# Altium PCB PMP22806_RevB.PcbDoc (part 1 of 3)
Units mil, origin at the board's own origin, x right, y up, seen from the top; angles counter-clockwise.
Board outline 5500 x 3040 mil, 4 copper layers (Top Layer, Signal Layer 1, Signal Layer 2, Bottom Layer), stack 61.2 mil thick; 196 components, 100 nets, 518 pads, 186 vias.
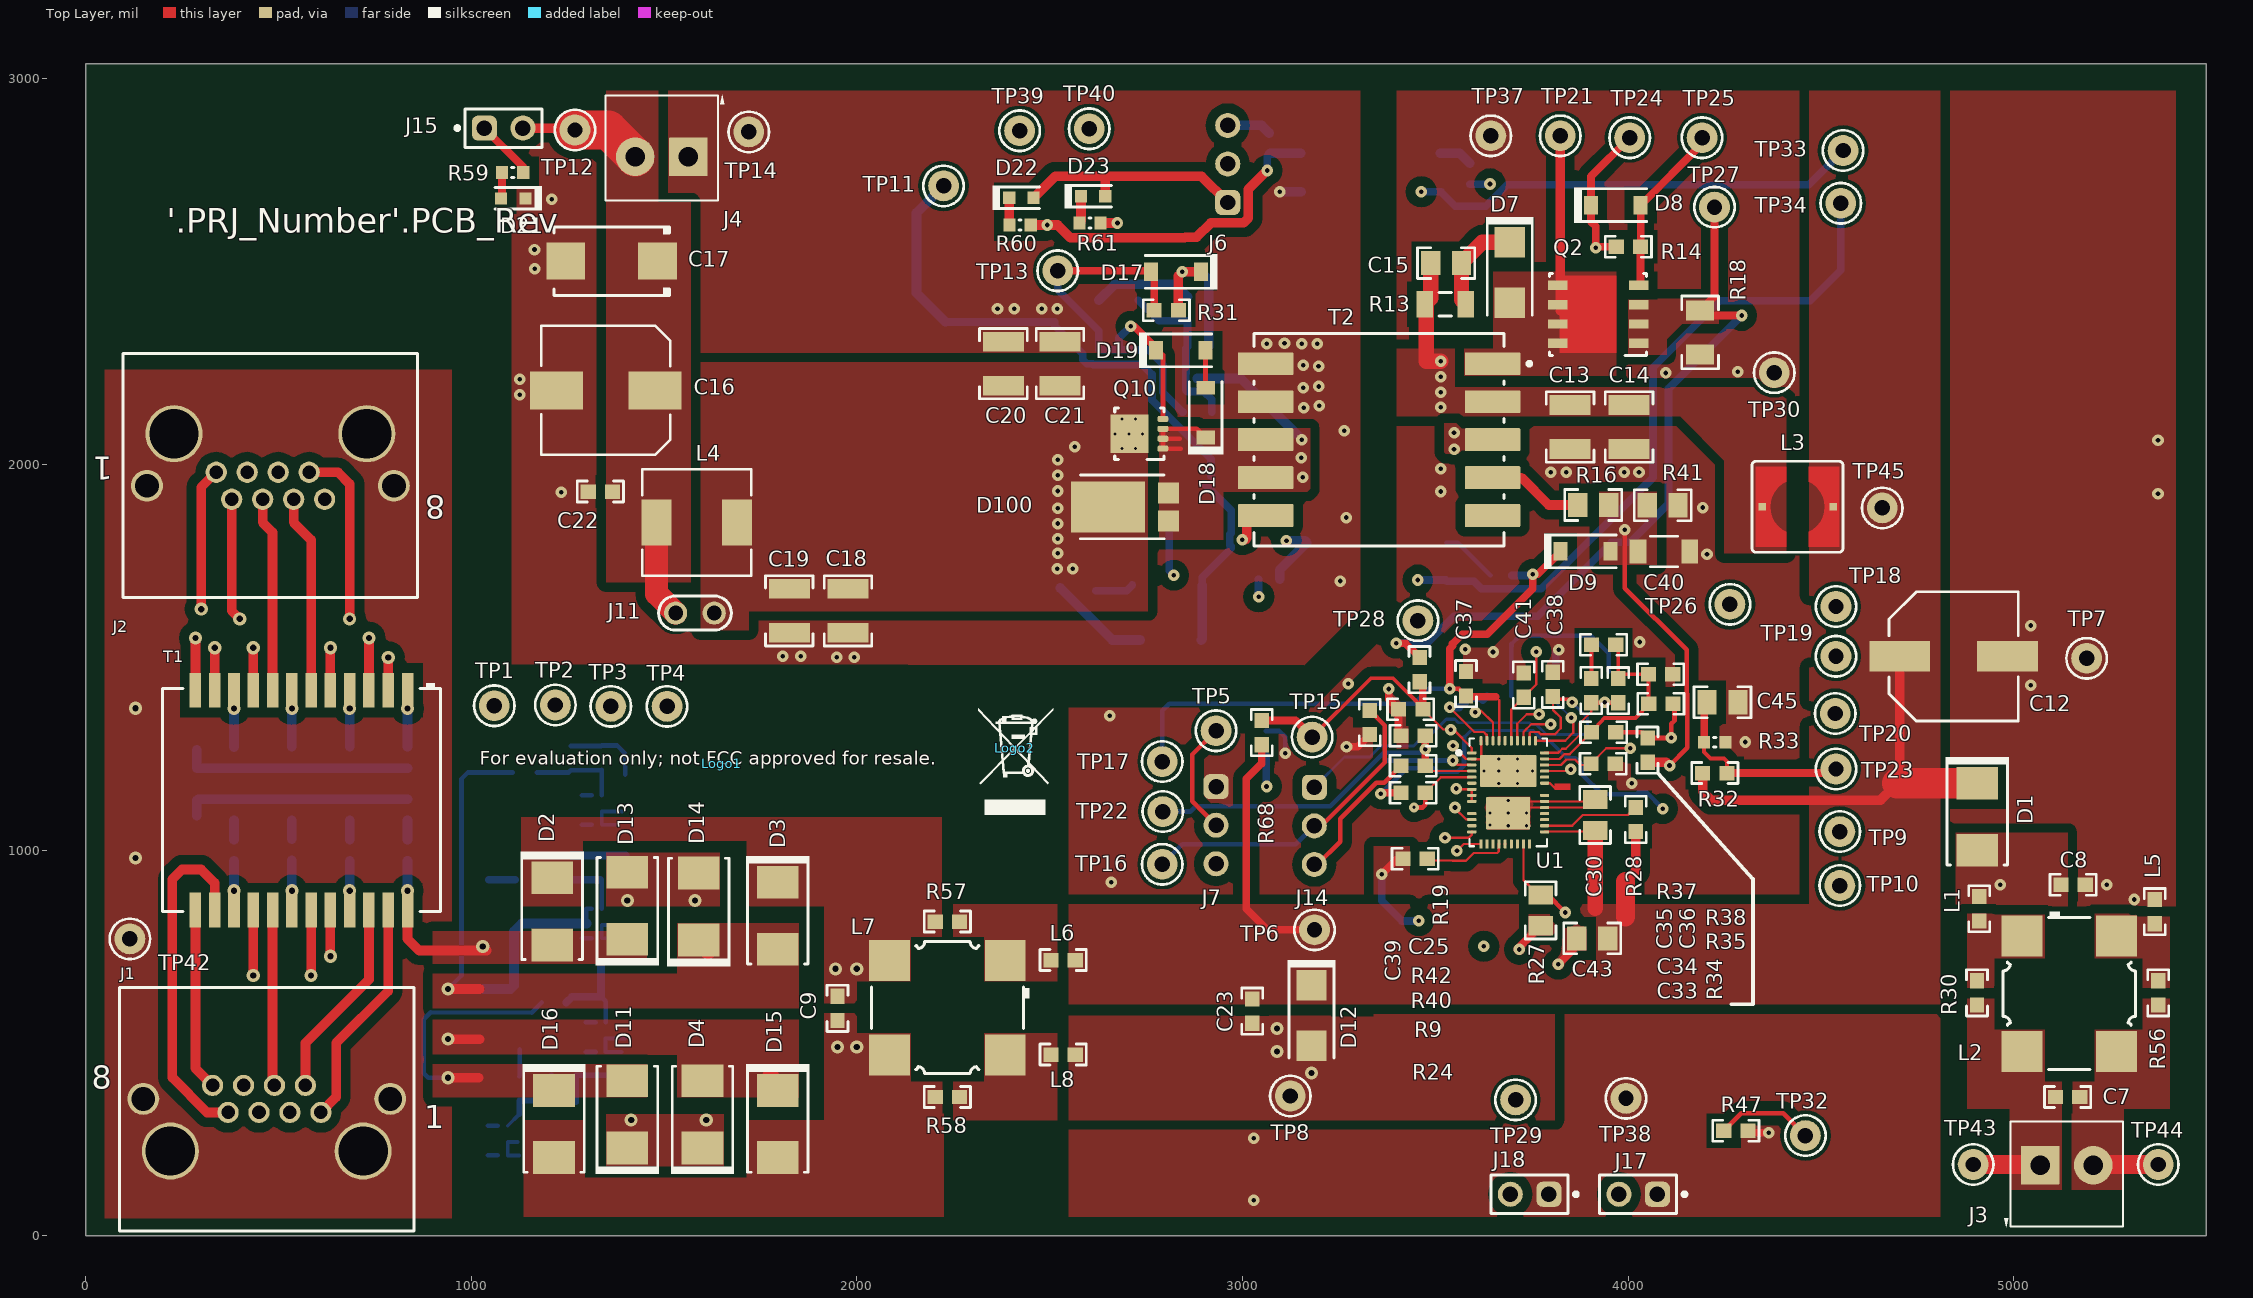
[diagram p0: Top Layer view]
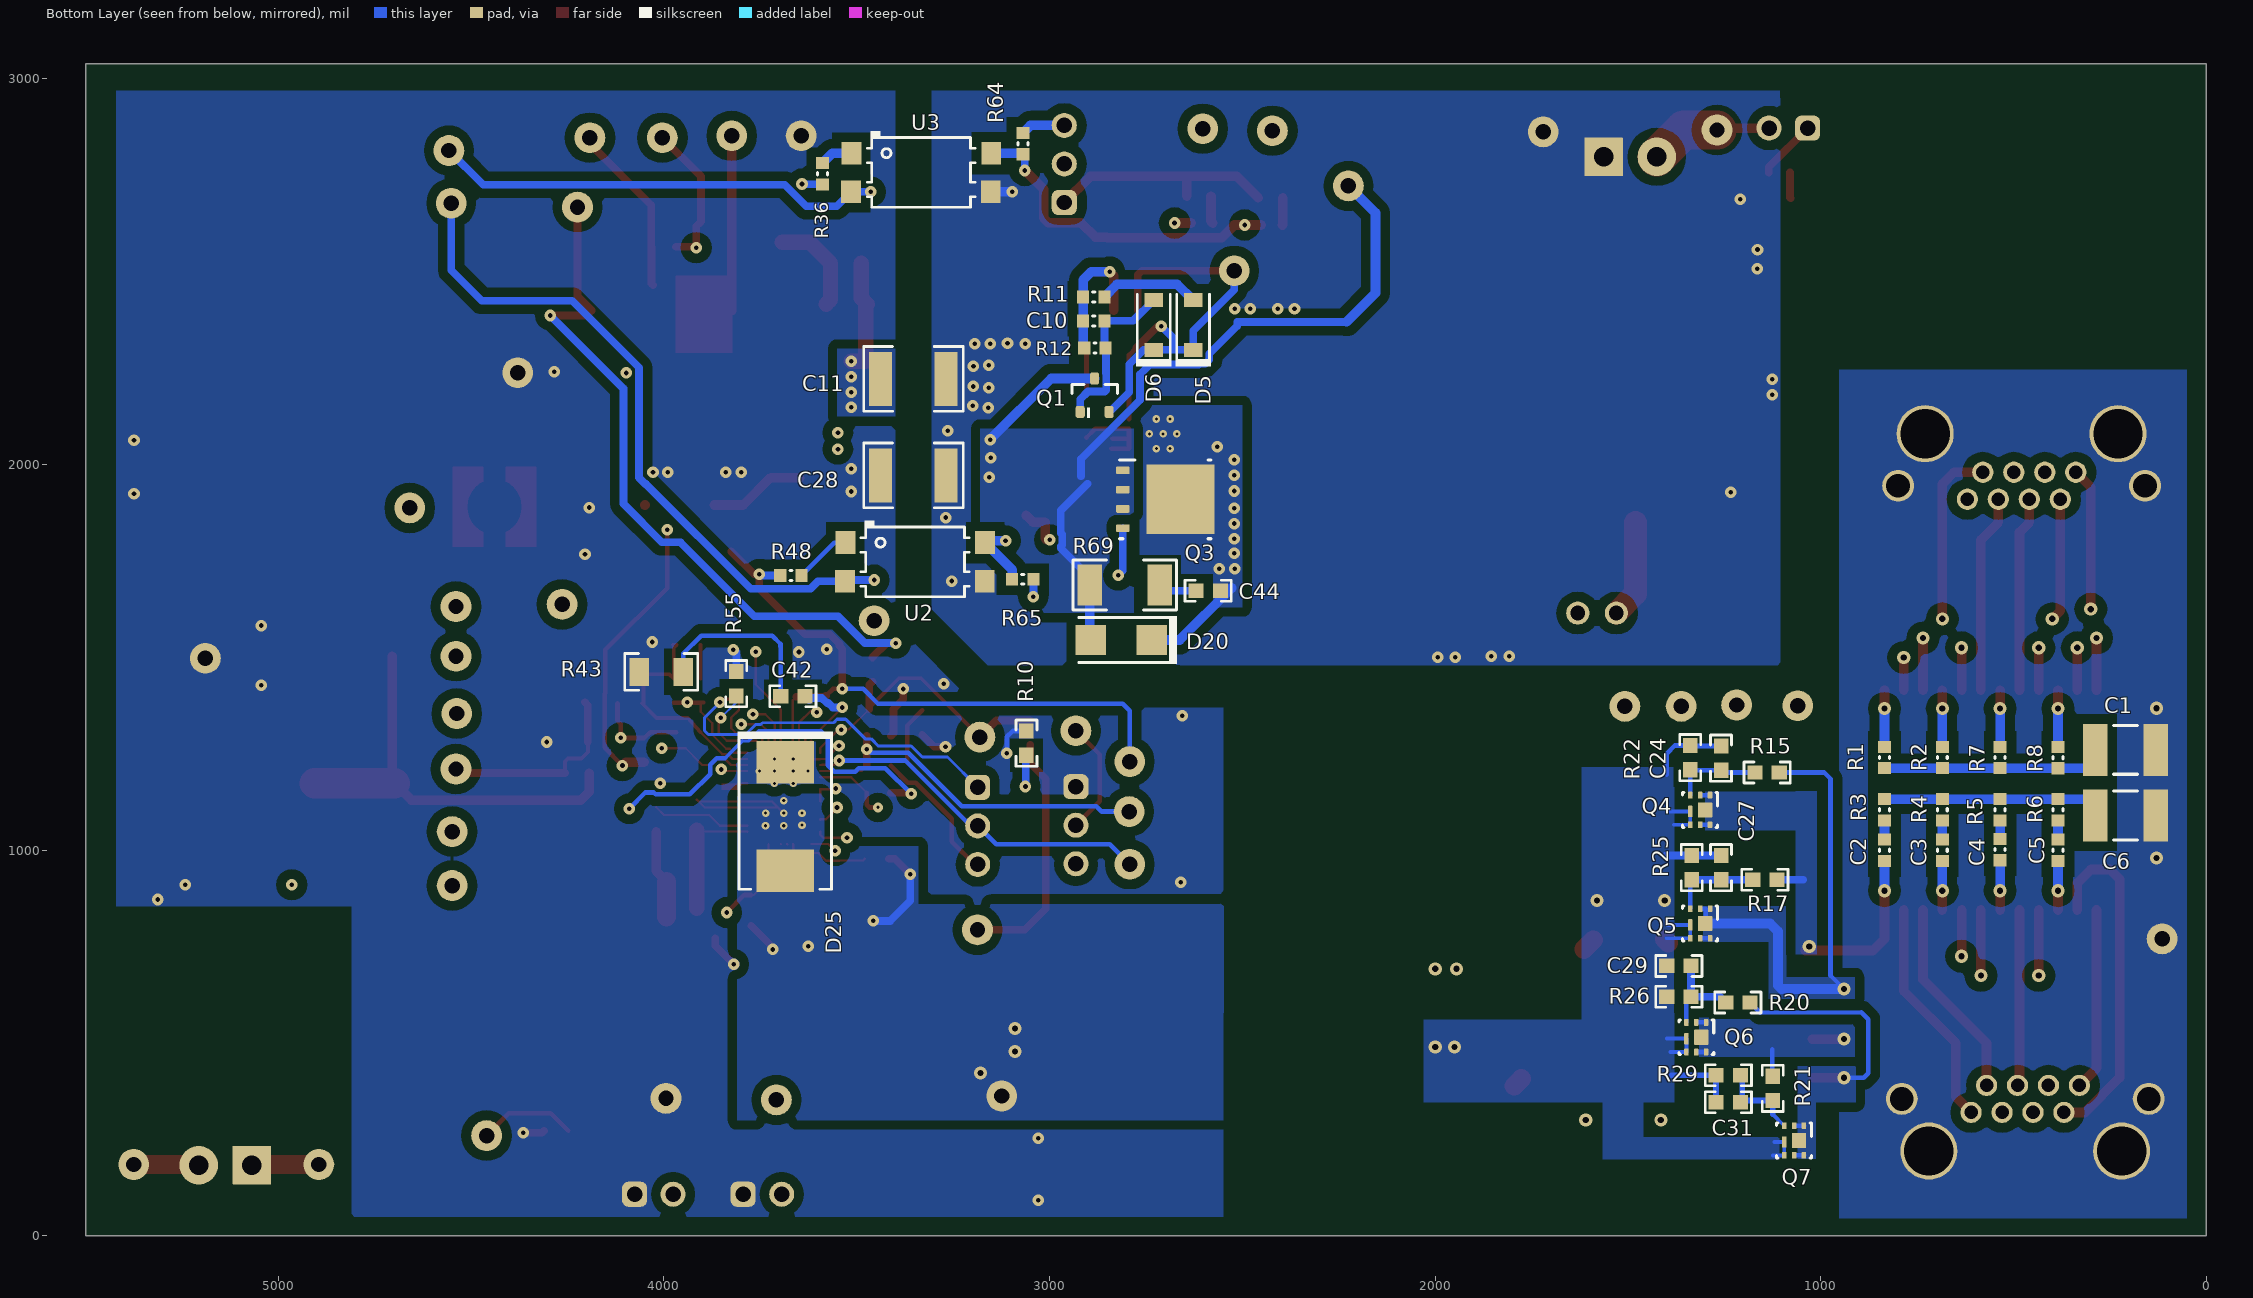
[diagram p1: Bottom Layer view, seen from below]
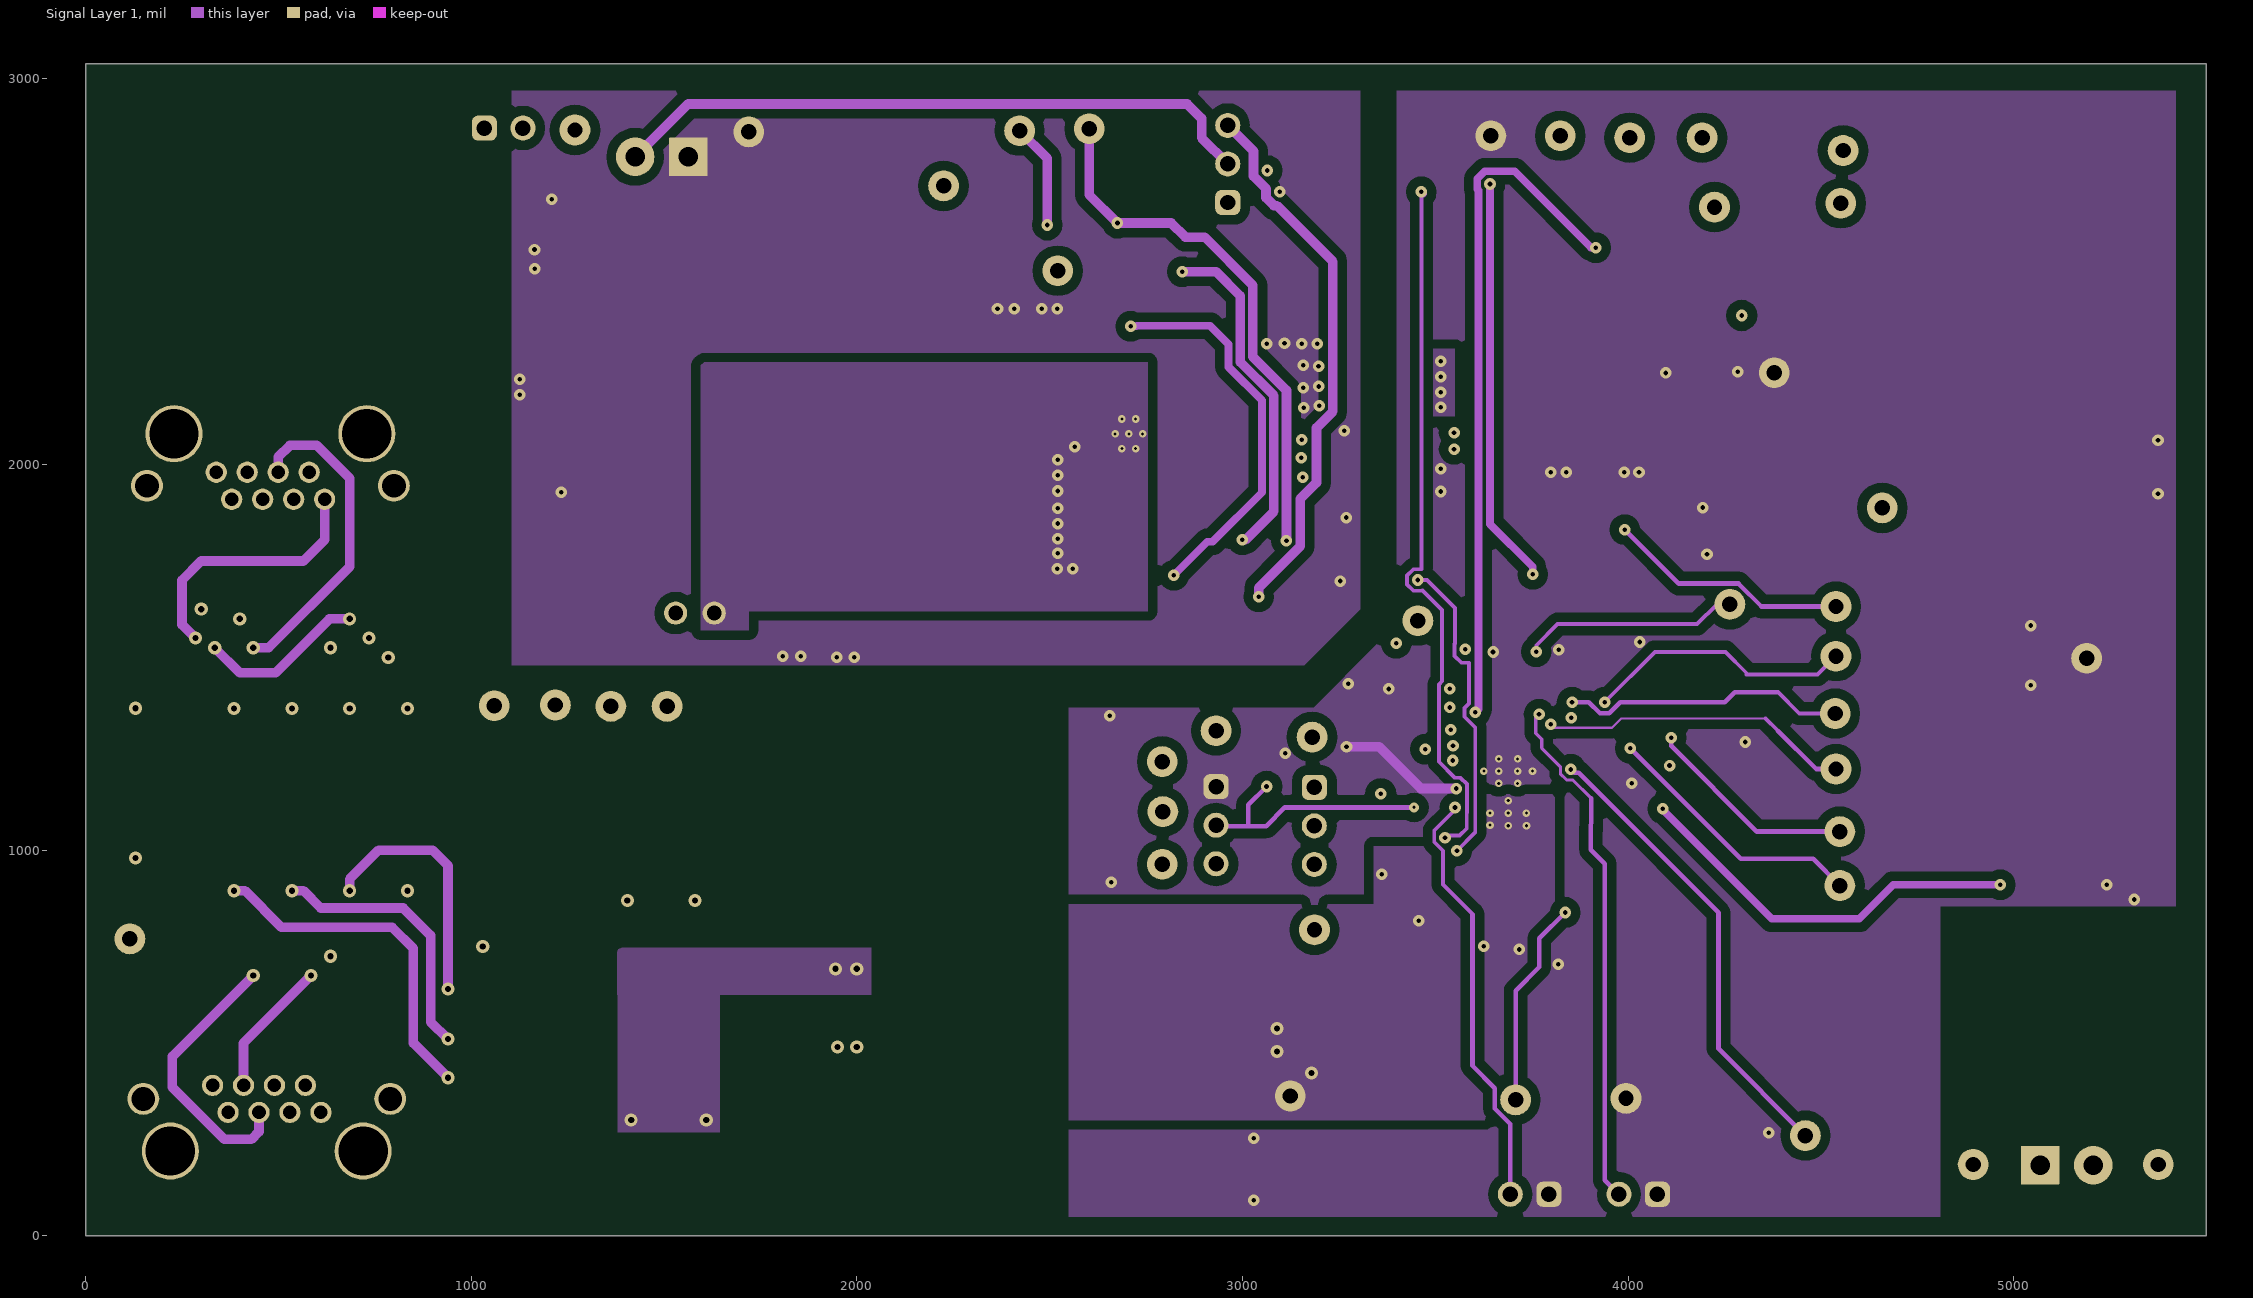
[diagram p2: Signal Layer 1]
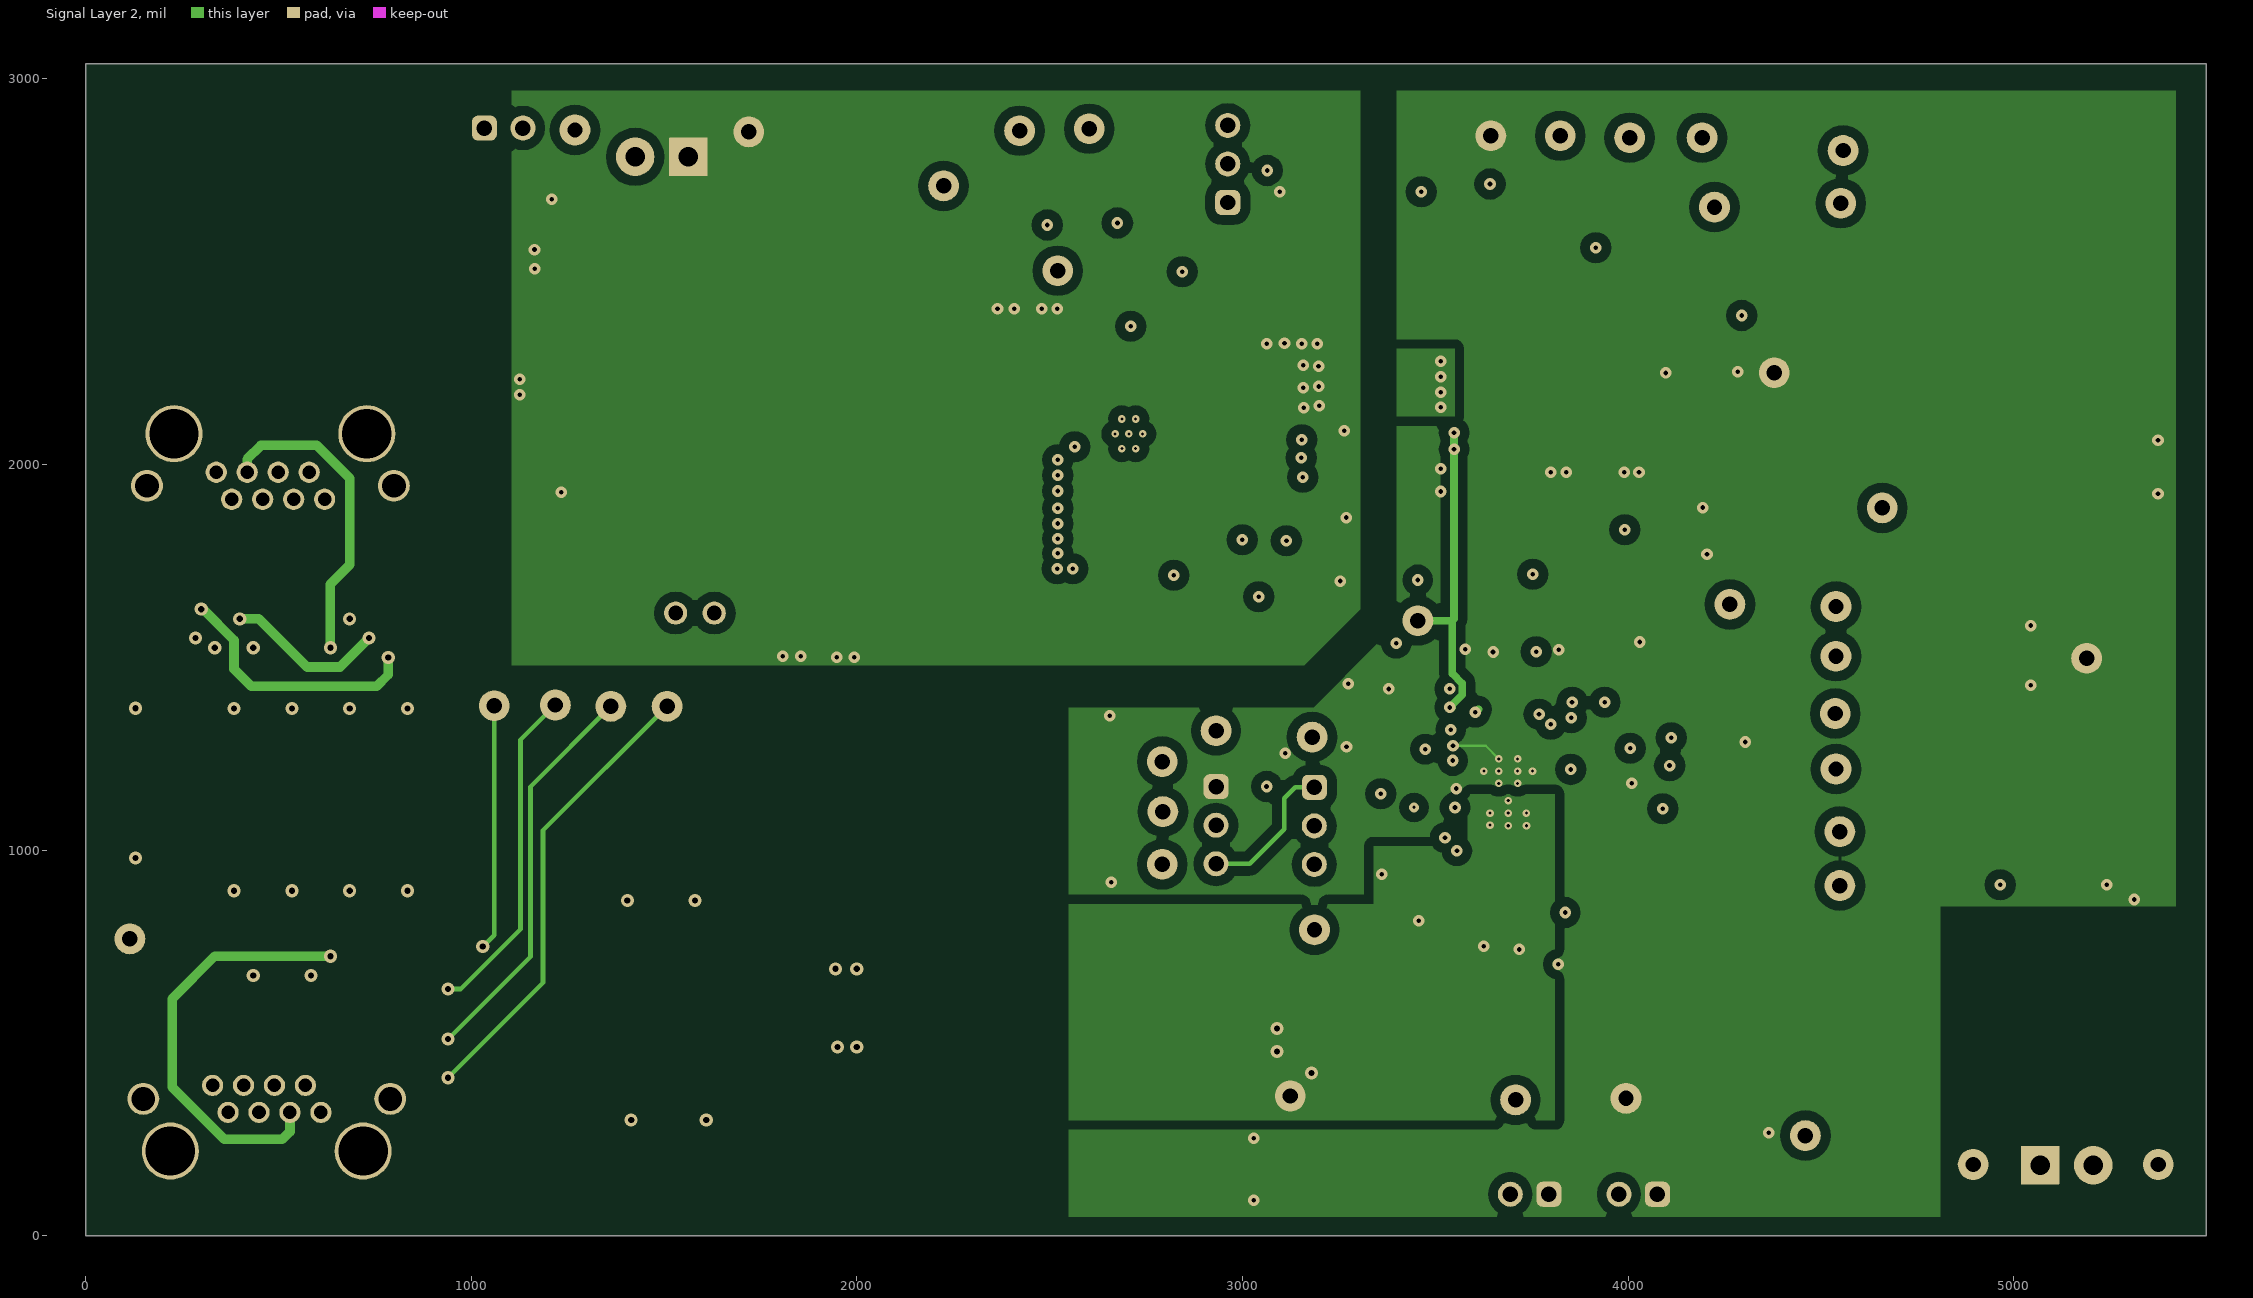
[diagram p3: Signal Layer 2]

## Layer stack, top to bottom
Top Solder: solder mask 0.4, Solder Resist, Dk 3.5
Top Layer: signal copper 2.8
Dielectric1: core 15, FR-4, Dk 4.8
Signal Layer 1: signal copper 2.8
Dielectric 2: prepreg 20, Dk 4.2
Signal Layer 2: signal copper 2.8
Dielectric 3: core 15, Dk 4.2
Bottom Layer: signal copper 2.8
Bottom Solder: solder mask 0.4, Solder Resist, Dk 3.5

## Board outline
0,0 5500,0 5500,3040 0,3040

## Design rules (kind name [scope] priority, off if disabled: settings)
AcuteAngle [All] p1: minimum=4.50000000000000E+0001 checktracksonly=FALSE
AssemblyTestPointUsage [All] p1: valid=2
BoardOutlineClearance BoardOutlineClearance_MountingHoles [OnCopper and InComponentClass('Mounting Holes')] p1: gap=39.37 ignorepadtopadclearanceinfootprint=FALSE
BoardOutlineClearance BoardOutlineClearance_Poly [OnCopper and IsPoly] p2: gap=25 ignorepadtopadclearanceinfootprint=FALSE
BoardOutlineClearance [OnCopper and Not InComponentClass('Logo') and not InComponentClass('FiducialMark') and not InRegion(1000,500,4000,800) and not InPoly] p3: gap=75 ignorepadtopadclearanceinfootprint=FALSE
Clearance Clearance_2 [InNamedPolygon('TOP_LAYER_BSP_P090')] p1: gap=60 ignorepadtopadclearanceinfootprint=FALSE
Clearance Clearance_1 [InNamedPolygon('BOTTOM_LAYER_BSP_P092')] p2: gap=60 ignorepadtopadclearanceinfootprint=FALSE
Clearance Clearance_Keepouts [((IsTrack Or IsArc) And Not InPoly) And IsFree and IsKeepOut vs ((IsTrack Or IsArc) And Not InPoly) And IsFree and IsKeepOut] p3: gap=0 ignorepadtopadclearanceinfootprint=FALSE
Clearance Clearance_Poly [InPolygon] p4: gap=25 ignorepadtopadclearanceinfootprint=TRUE
Clearance Clearance_FiducialMark [IsKeepOut and InComponentClass('FiducialMark') vs IsPad and InComponentClass('FiducialMark')] p5: gap=0 ignorepadtopadclearanceinfootprint=FALSE
Clearance [All] p6: gap=7.87 ignorepadtopadclearanceinfootprint=TRUE
ComponentClearance ComponentClearance_MountingHoles_FiducialMarks [InComponentClass('Mounting Holes') vs InComponentClass('FiducialMark')] p1: gap=50 collisioncheckmode=3 verticalgap=10 showdistances=FALSE
ComponentClearance ComponentClearance_Shunt [InComponentClass('Header') vs InComponentClass('Shunt')] p2: gap=0 collisioncheckmode=3 verticalgap=0 showdistances=FALSE
ComponentClearance ComponentClearance_Logo [InComponentClass('Logo')] p3: gap=50 collisioncheckmode=3 verticalgap=10 showdistances=FALSE
ComponentClearance ComponentClearance_ScrewToNut [(HasFootprint('NY PMS 440 0025 PH')) vs (HasFootprint('Keystone_1902C'))] p4: gap=5 collisioncheckmode=3 verticalgap=10 showdistances=FALSE
ComponentClearance ComponentClearance_MountingHoles [InComponentClass('Mounting Holes')] p5: gap=250 collisioncheckmode=3 verticalgap=100000 showdistances=FALSE
ComponentClearance ComponentClearance_SmallPassives [HasFootprint('0201*') or HasFootprint('0402*') or HasFootprint('0508') or HasFootprint('0603*') or HasFootprint('0612') or HasFootprint('0805*') or HasFootprint('0815*') or HasFootprint('0830*') or HasFootprint('1206*') or HasFootprint('1210*') or HasFootprint('1808*') or HasFootprint('1812*') or HasFootprint('1825*') or HasFootprint('2010*') or HasFootprint('2220*') or HasFootprint('2225*') or HasFootprint('2512*') or HasFootprint('2728*') or HasFootprint('3518*') vs HasFootprint('0201*') or HasFootprint('0402*') or HasFootprint('0508') or HasFootprint('0603*') or HasFootprint('0612') or HasFootprint('0805*') or HasFootprint('0815*') or HasFootprint('0830*') or HasFootprint('1206*') or HasFootprint('1210*') or HasFootprint('1808*') or HasFootprint('1812*') or HasFootprint('1825*') or HasFootprint('2010*') or HasFootprint('2220*') or HasFootprint('2225*') or HasFootprint('2512*') or HasFootprint('2728*') or HasFootprint('3518*')] p6: gap=14.96 collisioncheckmode=3 verticalgap=10 showdistances=FALSE
ComponentClearance ComponentClearance_THtoSMT [IsThruComponent vs IsSMTComponent] p7: gap=40 collisioncheckmode=3 verticalgap=30 showdistances=FALSE
ComponentClearance ComponentClearance_THtoTH [IsThruComponent vs IsThruComponent] p8: gap=30 collisioncheckmode=3 verticalgap=30 showdistances=FALSE
ComponentClearance [All] p9: gap=30 collisioncheckmode=3 verticalgap=10 showdistances=FALSE
DiffPairsRouting [All] p1: maxlimit=100 minlimit=10 mostfreqgap=10 toplayer_minwidth=15 toplayer_maxwidth=15 toplayer_prefwidth=15 midlayer1_minwidth=15 midlayer1_maxwidth=15 midlayer1_prefwidth=15 midlayer2_minwidth=15 midlayer2_maxwidth=15 midlayer2_prefwidth=15 bottomlayer_minwidth=15 bottomlayer_maxwidth=15 bottomlayer_prefwidth=15 maxuncoupledlength=1000
FabricationTestPointUsage TestPointUsage [All] p1: valid=2 allowmultiple=FALSE
FabricationTestpoint Testpoint [All] p1: side=3 testpointundercomponent=TRUE minsize=40 maxsize=100 preferedsize=60 minholesize=0 maxholesize=40 preferedholesize=32 testpointgrid=1 allowsidetop=TRUE allowsidebottom=TRUE usegrid=TRUE gridtolerance=0.01
FanoutControl Fanout_LCC [IsLCC] p1: bgadir=Out bgaviamode=Centered fanoutstyle=Auto fanoutdirection=Alternating viagrid=1 // Fanout_LCC (Default Rule)
FanoutControl Fanout_BGA [IsBGA] p2: bgadir=Out bgaviamode=Centered fanoutstyle=Auto fanoutdirection=Alternating viagrid=1 // Fanout_BGA (Default Rule)
FanoutControl Fanout_Default [All] p4: bgadir=Out bgaviamode=Centered fanoutstyle=Auto fanoutdirection=Alternating viagrid=1 // Fanout_Default (Default Rule)
FanoutControl Fanout_Small [(CompPinCount < 5)] p5: bgadir=Out bgaviamode=Centered fanoutstyle=Auto fanoutdirection=OutThenIn viagrid=1 // Fanout_Small (Default Rule)
Height [All] p1: minheight=0 maxheight=2500 prefheight=500
HoleSize [All] p1: absolutevalues=TRUE maxlimit=251 minlimit=7.87 maxpercent=80.000 minpercent=20.000
MinimumAnnularRing MinimumAnnularRing_ThermalPadVias [IsVia and InAnyComponent] p1: minimumring=5.91
MinimumAnnularRing [All] p2: minimumring=7.87
MinimumSolderMaskSliver MinimumSolderMaskSliver_Logo [InComponentClass('Logo') vs InComponentClass('Logo')] p1: minsoldermaskwidth=0.7
MinimumSolderMaskSliver [All] p2: minsoldermaskwidth=3.94
PlaneConnect [All] p1: planeconnectstyle=Relief reliefexpansion=10 reliefentries=4 reliefconductorwidth=10 reliefairgap=10
PolygonConnect [All] p1: connectstyle=Direct reliefconductorwidth=10 reliefentries=4 polygonreliefangle="90 Angle" airgapwidth=10
RoutingVias ThermalPadVias [IsVia and InAnyComponent] p1: holewidth=7.87 width=19.68 viastyle="Through Hole" minholewidth=7.87 minwidth=19.68 maxholewidth=12.99 maxwidth=23.62
RoutingVias [All] p2: holewidth=16 width=34 viastyle="Through Hole" minholewidth=7.87 minwidth=26 maxholewidth=40 maxwidth=65
SilkToBoardRegionClearance [Not ((IsComment or IsDesignator) And (Hide <> 'False')) and not InRegion(1000,500,4000,800)] p1:
SilkToSilkClearance SilkToSilkClearance_Pb-FreeLogo [(HasFootprint('Pb-Free_Overlay_Medium') OR HasFootprint('Pb-Free_Overlay_Small')) vs (HasFootprint('Pb-Free_Overlay_Medium') OR HasFootprint('Pb-Free_Overlay_Small'))] p1: silktosilkclearance=0
SilkToSilkClearance [All] p2: silktosilkclearance=3.94
SilkToSolderMaskClearance SilkToComponentPadClearance [(IsPad or IsFill or IsRegion) and InAnycomponent] p1: minsilkscreentomaskgap=5 clearancetoexposedcopper=TRUE
SilkToSolderMaskClearance "Silk to Solder Mask Opening" [All] p2: minsilkscreentomaskgap=3.94 clearancetoexposedcopper=FALSE
SolderMaskExpansion [All] p1: expansion=1.97
UnRoutedNet [All] p1: checkbadconnections=TRUE
Width [All] p1: maxlimit=100 minlimit=6 preferedwidth=10 checkconnectedcopper=TRUE
13 further rules are at their usual default settings.

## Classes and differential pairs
component class PMP22806_RevB_SH2: C10 C11 C12 C13 C14 C15 C16 C17 C18 C19 C20 C21 C22 C25 C28 C30 C33 C34 C35 C36 C37 C38 C39 C40 C41 C42 C43 C44 C45 D5 D6 D7 D8 D9 D12 D17 D18 D19 D20 D21 D22 D23 D25 D100 J4 J6 J11 J14 J15 J17 J18 L3 L4 Q1 Q2 Q3 Q10 R11 R12 R13 R14 R16 R18 R19 R24 R27 R28 R31 R32 R33 R34 R35 R36 R37 R38 R40 R41 R42 R43 R47 R48 R55 R59 R60 R61 R64 R65 R68 R69 T2 TP6 TP7 TP8 TP9 TP10 TP11 TP12 TP13 TP14 TP15 TP16 TP17 TP18 TP19 TP20 TP21 TP22 TP23 TP24 TP25 TP26 TP27 TP28 TP29 TP30 TP32 TP33 TP34 TP37 TP38 TP39 TP40 TP45 U1 U2 U3
component class PMP22806_RevB_SH1: C1 C2 C3 C4 C5 C6 C7 C8 C9 C23 C24 C27 C29 C31 D1 D2 D3 D4 D11 D13 D14 D15 D16 J1 J2 J3 J7 L1 L2 L5 L6 L7 L8 Logo1 Logo2 Q4 Q5 Q6 Q7 R1 R2 R3 R4 R5 R6 R7 R8 R9 R10 R15 R17 R20 R21 R22 R25 R26 R29 R30 R56 R57 R58 T1 TP1 TP2 TP3 TP4 TP5 TP42 TP43 TP44
component class Header: J6 J7 J14 J15 J17 J18

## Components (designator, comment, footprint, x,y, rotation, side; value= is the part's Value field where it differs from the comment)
C1 "GR443QR73D102KW01L" 1812 210,1260 r0 bottom value=1000pF
C2 "Capacitor" 0603L 835,1000 r90 bottom value=0.01uF
C3 "Capacitor" 0603L 685,1000 r90 bottom value=0.01uF
C4 "Capacitor" 0603L 535,1001.65 r90 bottom value=0.01uF
C5 "Capacitor" 0603L 385,1000 r90 bottom value=0.01uF
C6 "GR443QR73D102KW01L" 1812 210,1090 r180 bottom value=1000pF
C7 "C1608X7R2A102K080AA" 0603 5140,360 r0 top value=1000pF
C8 "C1608X7R2A102K080AA" 0603 5154.16,910.67 r0 top value=1000pF
C9 "C1608X7R2A102K080AA" 0603 1950,590 r270 top value=1000pF
C10 "GRM188R71H681KA01D" 0603L 2885.41,2372.69 r180 bottom value=680pF
C11 "Capacitor" 1812_HV 3353.21,2222.18 r0 bottom value=2200pF
C12 "EEE-FK1J330P" SM_RADIAL_F 4844.22,1502.61 r0 top value=33uF
C13 "Capacitor" 1210_270 3849.94,2097.54 r270 top value=2.2uF
C14 "Capacitor" 1210_270 4002.94,2097.62 r270 top value=2.2uF
C15 "Capacitor" 0805_HV 3528.21,2522.61 r180 top value=0.1uF
C16 "16SVP82M" SM_RADIAL_8MM 1349.22,2192.61 r180 top value=82uF
C17 "10TPE220ML" 7343-30 1364.22,2527.61 r180 top value=220uF
C18 "885012209028" 1210_220 1977.27,1620.69 r270 top value=10uF
C19 "885012209028" 1210_220 1825,1620.69 r270 top value=10uF
C20 "885012209028" 1210_220 2380,2261.56 r90 top value=10uF
C21 "885012209028" 1210_220 2526.98,2261.59 r90 top value=10uF
C22 "885012206076" 0603 1335,1930 r180 top value=1uF
C23 "C1608X7R2A102K080AA" 0603 3025.72,582.61 r270 top value=1000pF
C24 "GRM1885C1H331JA01D" 0603 1258.75,1238.87 r90 bottom value=330pF
C25 "GRM1885C1H331JA01D" 0603 3436.42,1365.64 r180 top value=330pF
C27 "GRM1885C1H331JA01D" 0603 1258.75,955 r90 bottom value=330pF
C28 "Capacitor" 1812_HV 3353.21,1972.18 r0 bottom value=2200pF
C29 "GRM1885C1H331JA01D" 0603 1368.28,700 r0 bottom value=330pF
C30 "Capacitor" 0805_HV 3914.73,1091.24 r90 top value=0.1uF
C31 "GRM1885C1H331JA01D" 0603 1240,346.26 r0 bottom value=330pF
C33 "GRM188R71E473KA01D" 0603 3935.34,1224.42 r180 top value=0.047uF
C34 "06035A560FAT2A" 0603 3936.83,1305.8 r180 top value=56pF
C35 "885012206087" 0603 3904.57,1414.08 r270 top value=4700pF
C36 "06035A100JAT2A" 0603 3974.57,1413.91 r270 top value=10pF
C37 "885012206076" 0603 3579.75,1431.74 r90 top value=1uF
C38 "885012206071" 0603 3805,1430 r270 top value=0.1uF
C39 "C0603C222K5RAC" 0603 3330.1,1331.19 r270 top value=2200pF
C40 "GRM31CR71E335KA88L" 1206_180 4092.97,1774.71 r0 top value=3.3uF
C41 "885012206071" 0603 3729.22,1428.35 r270 top value=0.1uF
C42 "885012206083" 0603 3665.54,1399.49 r0 bottom value=1000pF
C43 "Capacitor" 0805_HV 3907.37,771.27 r180 top value=0.1uF
C44 "06031C222KAT2A" 0603 2588.68,1672.97 r0 bottom value=2200pF
C45 "Capacitor" 0805_HV 4245,1383.63 r180 top value=0.1uF
D1 "CMP-0028397-2" SMB 4905.66,1086.67 r270 top value=100V
D2 "CMP-0028397-2" SMB 1210,841.48 r270 top value=100V
D3 "CMP-0028397-2" SMB 1795,830 r270 top value=100V
D4 "CMP-0028397-2" SMB 1600,315 r90 top value=100V
D5 "MMSD4148T1G" SOD-123 2627.76,2361.87 r90 bottom value=100V
D6 "MMSD4148T1G" SOD-123 2730,2361.87 r90 bottom value=100V
D7 "ES1D-13-F" SMA 3693.21,2497.93 r270 top value=200V
D8 "MMSD4148T1G" SOD-123 3968.21,2672.93 r0 top value=100V
D9 "MMSD4148T1G" SOD-123 3889.78,1774.71 r0 top value=100V
D11 "CMP-0028397-2" SMB 1405,315 r90 top value=100V
D12 "SMAJ58A-13-F" SMA 3179.22,571.3 r270 top value=58V
D13 "CMP-0028397-2" SMB 1405,856 r90 top value=100V
D14 "CMP-0028397-2" SMB 1590,854 r90 top value=100V
D15 "CMP-0028397-2" SMB 1795,290 r270 top value=100V
D16 "CMP-0028397-2" SMB 1215,290 r270 top value=100V
D17 "MMSD4148T1G" SOD-123 2827.83,2499.71 r180 top value=100V
D18 "MMSZ5242B-7-F" SOD-123 2904.38,2134.71 r90 top value=12V
D19 "MMSZ5242B-7-F" SOD-123 2840.12,2296.08 r0 top value=12V
D20 "3SMAJ5934B-TP" SMA 2814.21,1545 r0 bottom value=24V
D21 "150060YS75000" WL-SMCW_YELLOW 1109.22,2690.36 r180 top value=Yellow
D22 "150060YS75000" WL-SMCW_YELLOW 2427,2691.83 r0 top value=Yellow
D23 "150060YS75000" WL-SMCW_YELLOW 2613,2695.76 r0 top value=Yellow
D25 "B3100-13-F" SMC 3685.52,1087.47 r270 bottom value=100V
D100 "SBR8A60P5-13" POWERDI5 2730,1890 r180 top value=60V
J1 "1-406541-1" TEC_1-406541-1 470.32,327.05 r0 top
J2 "1-406541-1" TEC_1-406541-1 479.06,1972.99 r180 top
J3 "ED555/2DS" TERM_BLK_ED555-2DS 5068.66,183.14 r0 top
J4 "Receptacle_2x1" TERM_BLK_ED555-2DS 1563.21,2797.98 r180 top
J6 "TSW-103-07-G-S" TSW-103-07-G-S 2962.05,2779.62 r90 top
J7 "TSW-103-07-G-S" TSW-103-07-G-S 2931.67,1064.8 r270 top
J11 "923345-01-C" 3M_923345-01-C 1580.32,1615 r180 top
J14 "TSW-103-07-G-S" TSW-103-07-G-S 3186.48,1063.15 r270 top
J15 "TSW-102-07-G-S" TSW-102-07-G-S 1084.22,2872.61 r0 top
J17 "TSW-102-07-G-S" TSW-102-07-G-S 4026.26,107.87 r180 top
J18 "TSW-102-07-G-S" TSW-102-07-G-S 3744.73,107.87 r180 top
L1 "CMP-0003192-2" 0603 4910.66,848.17 r90 top value="300 ohm"
L2 "744272251" WE-SL5 5144.22,628.14 r0 top value=250uH
L3 "744042003" WE-TPC-M1 4439.38,1890.61 r180 top value=3.3uH
L4 "744302015" WE-HCM_7050 1585,1850 r180 top value=150nH
L5 "CMP-0003192-2" 0603 5365.66,840.74 r90 top value="300 ohm"
L6 "CMP-0003192-2" 0603 2535,715 r0 top value="300 ohm"
L7 "744272251" WE-SL5 2235,591.75 r270 top value=250uH
L8 "CMP-0003192-2" 0603 2535,470 r0 top value="300 ohm"
Logo1 "FCC disclaimer" FCC_disclaimer 1650,1224.42 r0 top
Logo2 "WEEE logo" WEEE_Minimum 2410,1264.21 r0 top
Q1 "MMBT3906-7-F" SOT-23L 2883.21,2179.9 r90 bottom value="40 V"
Q2 "FDMS86252" TRANS_Fairchild_PQFN08A 3922.5,2389.71 r180 top value=150V
Q3 "CSD18504Q5A" DQJ0008A 2700.04,1910 r180 bottom value=40V
Q4 "CSD19538Q2" DQK0006C 1313,1104.48 r270 bottom value=100V
Q5 "CSD19538Q2" DQK0006C 1312.95,810 r270 bottom value=100V
Q6 "CSD19538Q2" DQK0006C 1323,515 r270 bottom value=100V
Q7 "CSD19538Q2" DQK0006C 1069.38,247.14 r270 bottom value=100V
Q10 "CSD17577Q3A" DNH0008A 2732.92,2079.81 r180 top value=30V
R1 "Resistor" 0603L 835,1240.32 r270 bottom value=75.0
R2 "Resistor" 0603L 685,1240.32 r270 bottom value=75.0
R3 "Resistor" 0603L 835,1105 r270 bottom value=75.0
R4 "Resistor" 0603L 685,1105 r270 bottom value=75.0
R5 "Resistor" 0603L 535,1105 r270 bottom value=75.0
R6 "Resistor" 0603L 385,1105 r270 bottom value=75.0
R7 "Resistor" 0603L 535,1240.32 r270 bottom value=75.0
R8 "Resistor" 0603L 385,1240 r90 bottom value=75.0
R9 "CRCW0603100KFKEA" 0603 3442.75,1149.02 r180 top value=100k
R10 "CRCW06034K42FKEA" 0603 3060.14,1277.73 r270 bottom value=4.42k
R11 "Resistor" 0603L 2885.41,2434.9 r180 bottom value=4.7
R12 "CRCW06034K99FKEA" 0603L 2882.61,2302.69 r0 bottom value=4.99k
R13 "Resistor" 1206L 3526.21,2416.2 r180 top value=39k
R14 "CRCW06034R70JNEA" 0603 4000.97,2564.71 r0 top value=4.7
R15 "CMP-0022138-4" 0603 1139.24,1201.52 r180 bottom value=1.00Meg
R16 "ERJ-6RQF3R9V" 0805_HV 3909.78,1895.16 r180 top value=3.90
R17 "CMP-0022138-4" 0603 1145,923.5 r180 bottom value=1.00Meg
R18 "ERJ-8RQFR12V" 1206 4186.94,2342.61 r270 top value=0.12
R19 "RC0603FR-071KL" 0603 3459.5,1468.47 r90 top value=1.00k
R20 "CMP-0022138-4" 0603 1215,605 r180 bottom value=1.00Meg
R21 "CMP-0022138-4" 0603 1125,382.17 r90 bottom value=1.00Meg
R22 "CMP-0022224-4" 0603 1338.75,1240 r270 bottom value=232k
R24 "CRCW060349K9FKEA" 0603 3447.69,977.61 r0 top value=49.9k
R25 "CMP-0022224-4" 0603 1335,955 r270 bottom value=232k
R26 "CMP-0022224-4" 0603 1368.28,620.29 r180 bottom value=232k
R27 "CRCW080531R6FKEA" 0805_HV 3773.43,843.95 r90 top value=31.6
R28 "RC0603FR-0725K5L" 0603 4019.73,1079.66 r90 top value=25.5k
R29 "CMP-0022224-4" 0603 1240.05,416.62 r180 bottom value=232k
R30 "ERJ-3GEY0R00V" 0603 4905,630 r90 top value=0
R31 "CRCW060310R0FKEA" 0603 2802.58,2399.9 r0 top value=10.0
R32 "CRCW0603110KFKEA" 0603 4225,1200 r180 top value=110k
R33 "CRCW060310K0FKEA" 0603L 4225,1280 r0 top value=10.0k
R34 "CRCW060310R0JNEA" 0603 4050.71,1259.42 r90 top value=10
R35 "RC0603FR-0724K9L" 0603 4085,1380 r0 top value=24.9k
R36 "CRCW060310K0FKEA" 0603L 3589.22,2754.26 r270 bottom value=10.0k
R37 "CRCW0603100KFKEA" 0603 3936.46,1532.61 r0 top value=100k
R38 "CRCW06034K32FKEA" 0603 4084.45,1456.11 r0 top value=4.32k
R40 "RC0603FR-07237KL" 0603 3442.75,1219.02 r0 top value=237k
R41 "CRCW08053K30JNEA" 0805_HV 4089.78,1894.71 r180 top value=3.3k
R42 "CRCW060360K4FKEA" 0603 3442.75,1296.91 r0 top value=60.4k
R43 "CRCW120651R0JNEA" 1206 4006.93,1462.61 r180 bottom value=51
R47 "CRCW0603499KFKEA" 0603 4279.73,272.61 r180 top value=499k
R48 "CRCW060310K0FKEA" 0603L 3670.77,1712.61 r0 bottom value=10.0k
R55 "ERJ-3GEY0R00V" 0603 3812.78,1431.74 r90 bottom value=0
R56 "ERJ-3GEY0R00V" 0603 5375,630 r90 top value=0
R57 "ERJ-3GEY0R00V" 0603 2235,815 r0 top value=0
R58 "ERJ-3GEY0R00V" 0603 2235,360 r0 top value=0
R59 "CRCW060310K0FKEA" 0603L 1107.72,2757.61 r0 top value=10.0k
R60 "CRCW060310K0FKEA" 0603L 2423.5,2621.31 r180 top value=10.0k
R61 "CRCW060310K0FKEA" 0603L 2604.73,2626.47 r180 top value=10.0k
R64 "CRCW060310K0FKEA" 0603L 3069.22,2832.2 r90 bottom value=10.0k
R65 "CRCW060310K0FKEA" 0603L 3069.55,1702.61 r180 bottom value=10.0k
R68 "CRCW0603750KFKEA" 0603 3050,1305 r90 top value=750k
R69 "CRCW20107R50JNEF" 2010 2805,1687.53 r180 bottom value=7.5
T1 "7490220122" Wurth_7490220122 560,1130 r270 top value=350uH
T2 "LDT1038-50R" FP-LDT1038-50R_SMD10-MFG 3354.38,2064.71 r90 top
TP1 "5000" Keystone5000 1060,1374.68 r90 top
TP2 "5001" Keystone5001 1218.39,1376.5 r90 top
TP3 "5002" Keystone5002 1362.2,1373.03 r90 top
TP4 "5003" Keystone5003 1508,1373.03 r90 top
TP5 "5002" Keystone5002 2931.67,1309.85 r90 top
TP6 "5000" Keystone5000 3186.99,793.5 r90 top
TP7 "5001" Keystone5001 5189.22,1497.61 r90 top
TP8 "5001" Keystone5001 3124.22,362.61 r90 top
TP9 "5002" Keystone5002 4549.22,1048.37 r90 top
TP10 "5002" Keystone5002 4549.22,908.37 r90 top
TP11 "5003" Keystone5003 2225,2722.59 r90 top
TP12 "5000" Keystone5000 1269.22,2867.61 r90 top
TP13 "5003" Keystone5003 2521.03,2502.61 r90 top
TP14 "5001" Keystone5001 1719.93,2862.61 r90 top
TP15 "5002" Keystone5002 3180.79,1293.42 r90 top
TP16 "5002" Keystone5002 2792.1,963.44 r270 top
TP17 "5002" Keystone5002 2792.1,1229.86 r90 top
TP18 "5000" Keystone5000 4539.31,1631.92 r90 top
TP19 "5002" Keystone5002 4539.22,1502.89 r90 top
TP20 "5002" Keystone5002 4537.31,1354.42 r90 top
TP21 "5003" Keystone5003 3824.22,2852.61 r90 top
TP22 "5002" Keystone5002 2793.64,1100.21 r180 top
TP23 "5002" Keystone5002 4539.31,1210.56 r90 top
TP24 "5002" Keystone5002 4004.22,2847.61 r90 top
TP25 "5002" Keystone5002 4191.94,2847.61 r90 top
TP26 "5002" Keystone5002 4264.22,1637.61 r90 top
TP27 "5002" Keystone5002 4224.22,2667.61 r90 top
TP28 "5003" Keystone5003 3455.12,1595.17 r90 top
TP29 "5003" Keystone5003 3708.39,352.55 r90 top
TP30 "5001" Keystone5001 4379.22,2238.29 r90 top
TP32 "5002" Keystone5002 4460,260 r90 top
TP33 "5003" Keystone5003 4557.62,2814.41 r0 top
TP34 "5003" Keystone5003 4551.67,2677.61 r0 top
TP37 "5001" Keystone5001 3644.22,2852.61 r90 top
TP38 "5001" Keystone5001 3994.73,356.49 r90 top
TP39 "5003" Keystone5003 2422.24,2865.69 r90 top
TP40 "5003" Keystone5003 2602.77,2870.85 r90 top
TP42 "5003" Keystone5003 115,770 r90 top
TP43 "5000" Keystone5000 4895,185 r90 top
TP44 "5001" Keystone5001 5375,185 r90 top
TP45 "5000" Keystone5000 4659.22,1887.61 r90 top
U1 "TPS23731RMT" RMT0045A-MFG 3689.34,1150.05 r0 top
U2 "FOD817DS" N04C 3348.8,1747.61 r180 bottom
U3 "FOD817DS" N04C 3333.21,2757.61 r180 bottom

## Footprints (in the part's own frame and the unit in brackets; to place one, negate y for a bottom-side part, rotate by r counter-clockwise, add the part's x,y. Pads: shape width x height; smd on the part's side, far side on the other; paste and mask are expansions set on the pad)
3M_923345-01-C [mil] "Wire Jumper"
  round 60 hole 38: 1(-50,0) 2(50,0)
  silkscreen extent -94,-44 94,44, body extent -63,-13 63,13, height 74
0603 [mm] "0603 from SM-752 data"
  rect 1x0.95 smd: 1(-0.8,0) 2(0.8,0)
  silkscreen extent -1.52,-0.69 1.52,0.69, body extent -0.87,-0.47 0.87,0.47, height 1
0603L [mm] "0603 from SM-752 data"
  rect 0.8x0.85 smd: 1(-0.7,0) 2(0.7,0)
  silkscreen extent -0.07,-0.33 0.07,0.33, body extent -0.87,-0.47 0.87,0.47, height 1
0805_HV [mil] "0805 with 30mil clearance between pads"
  rect 50x63 smd: 1(-40,0) 2(40,0)
  silkscreen extent -74,-40 74,40, body extent -43,-29 43,29, height 57
1206 [mm] "1206 from SM-752 data"
  rect 1.3x1.85 smd: 1(-1.45,0) 2(1.45,0)
  silkscreen extent -2.4,-1.21 2.4,1.21, body extent -1.7,-0.9 1.7,0.9, height 1.35
1206_180 [mm] "1206_180"
  rect 1.1x1.6 smd: 1(-1.7,0) 2(1.7,0)
  silkscreen extent -0.9,-1 0.9,1, body extent -1.75,-0.95 1.75,0.95, height 1.8
1206L [mm] "1206 from SM-752 data"
  rect 1.1x1.75 smd: 1(-1.35,0) 2(1.35,0)
  silkscreen extent -0.4,-0.77 0.4,0.77, body extent -1.7,-0.9 1.7,0.9, height 1.35
1210_220 [mm] "1210"
  rect 1.3x2.7 smd: 1(-1.45,0) 2(1.45,0)
  silkscreen extent -2.32,-1.57 2.32,1.57, body extent -1.7,-1.35 1.7,1.35, height 2.2
1210_270 [mm] "1210"
  rect 1.3x2.7 smd: 1(-1.45,0) 2(1.45,0)
  silkscreen extent -2.32,-1.57 2.32,1.57, body extent -1.7,-1.35 1.7,1.35, height 2.7
1812 [mm]
  rect 1.6x3.4 smd: 1(-2,0) 2(2,0)
  silkscreen extent -0.8,-1.6 0.8,1.6, body extent -2.4,-1.7 2.4,1.7, height 1.35
1812_HV [mil] "PRG recommended land pattern"
  rect 60x140 smd: 1(-85,0) 2(85,0)
  silkscreen extent -129,-84 129,84, body extent -94,-67 94,67, height 53
2010 [mm] "Chip Capacitor, Body 5.08x2.54mm, IPC Medium Density"
  rect 1.6x2.7 smd: 1(-2.3,0) 2(2.3,0)
  silkscreen extent -3.42,-1.65 3.42,1.65, body extent -2.73,-1.45 2.73,1.45, height 1.66
7343-30 [mm] "Medium Density based on Kemet T495 dimensions"
  rect 2.55x2.45 smd: 1(-3.025,0) 2(3.025,0)
  silkscreen extent -3.8,-2.25 3.8,2.25, body extent -3.8,-2.3 3.8,2.3, height 3.1
DNH0008A [mm] "VSONP-8"
  rrect50% 0.7x0.4 smd paste-0.05 mask-0.05: 1(-1.55,0.975) 2(-1.55,0.325) 3(-1.55,-0.325) 4(-1.55,-0.975) 5(1.55,-0.975) 6(1.55,-0.325) 7(1.55,0.325) 8(1.55,0.975)
  rrect4% 2.51x2.55 smd paste-1.5 mask-1.5: 9(0.645,0)
  rrect14% 0.705x1.125 on Top Paste: 9A(-0.208,0.662) 9B(0.697,0.662) 9C(-0.208,-0.663) 9D(0.697,-0.663)
  silkscreen extent -1.62,-1.7 1.62,1.7, body extent -1.65,-1.65 1.65,1.66, height 0.91
DQJ0008A [mm] "SMD, 8-Leads, Body 5.75x4.9mm"
  rrect39% 0.91x0.51 smd paste-0.05 mask-0.05: 1(-2.795,1.905) 2(-2.795,0.635) 3(-2.795,-0.635) 4(-2.795,-1.905) 5(2.795,-1.905) 6(2.795,-0.635) 7(2.795,0.635) 8(2.795,1.905)
  rrect8% 1.58x1.25 on Bottom Paste: 9(-0.38,-1.45) 9(-0.38,0) 9(-0.38,1.45) 9(1.4,-1.45) 9(1.4,0) 9(1.4,1.45)
  rrect3% 3.48x4.47 on Bottom Solder: 9(0.55,0)
  rrect2% 4.49x4.57 smd paste-2.5 mask-2.5: 9(1.005,0)
  silkscreen extent -3,-2.6 3,2.6, body extent -3.13,-2.45 3.13,2.45, height 1.15
DQK0006C [mm] "WSON"
  rrect12% 0.9x0.86 on Bottom Paste: 0(0,0.325)
  rrect34% 0.7x0.29 on Bottom Paste: 0(0.095,-0.65)
  rrect33% 0.45x0.3 smd: 1(-0.975,0.65) 2(-0.975,0) 3(-0.975,-0.65) 4(0.975,-0.65) 5(0.975,0) 6(0.975,0.65)
  rrect33% 0.75x0.3 smd paste-0.15: 7(0.095,-0.65)
  rrect11% 1x0.95 smd paste-0.5: 8(0,0.325)
  silkscreen extent -1.15,-1.15 1.15,1.15, body extent -1,-1 1,1, height 0.82
FCC_disclaimer [mil]
FP-LDT1038-50R_SMD10-MFG [mm]
  rrect7% 1.5x3.65 smd paste+0 mask+0: 1(5,-7.475) 2(2.5,-7.475) 3(0,-7.475) 4(-2.5,-7.475) 5(-5,-7.475) 6(-5,7.475) 7(-2.5,7.475) 8(0,7.475) 9(2.5,7.475) 10(5,7.475)
  silkscreen extent -7,-10.03 7,8.23, body extent -7.1,-9.4 7.1,9.4, height 0.25
Keystone5000 [mil] "For Keystone 500x miniature loop terminals"
  round 80 hole 40: 1(0,0)
  silkscreen extent -52,-52 52,52, body extent -49,-49 49,49, height 182
Keystone5001 [mil] "For Keystone 500x miniature loop terminals"
  round 80 hole 40: 1(0,0)
  silkscreen extent -52,-52 52,52, body extent -49,-49 49,49, height 182
Keystone5002 [mil] "For Keystone 500x miniature loop terminals"
  round 80 hole 40: 1(0,0)
  silkscreen extent -52,-52 52,52, body extent -49,-49 49,49, height 182
Keystone5003 [mil] "For Keystone 500x miniature loop terminals"
  round 80 hole 40: 1(0,0)
  silkscreen extent -52,-52 52,52, body extent -49,-49 49,49, height 182
N04C [mm] "FAIRCHILD"
  rect 1.3x1.5 smd mask+0.065: 1(-4.587,1.27) 2(-4.612,-1.27) 3(4.588,-1.27) 4(4.613,1.27)
  silkscreen extent -3.56,-2.3 3.56,2.72, body extent -5.08,-2.3 5.08,2.29, height 3.87
POWERDI5 [mm] "Diodes Inc recommended land pattern, ap02001.pdf rev 60"
  rect 1.4x1.39 smd: 1(-1.991,0.92) 2(-1.991,-0.92)
  rect 4.86x3.36 smd: 3(1.991,0)
  silkscreen extent -1.7,-2.1 3.8,2.1, body extent -2.27,-2.03 4.33,2.03, height 1.17
RMT0045A-MFG [mm]
  rrect50% 0.6x0.2 smd paste+0 mask+0: 1(-2.4,2.6) 2(-2.4,2.2) 3(-2.4,1.8) 4(-2.4,1.4) 5(-2.4,1) 6(-2.4,0.6) 7(-2.4,0.2) 8(-2.4,-0.2) 9(-2.4,-0.6) 10(-2.4,-1.4) 11(-2.4,-1.8) 12(-2.4,-2.2) 13(-2.4,-2.6) 23(2.4,-2.6) 24(2.4,-2.2) 25(2.4,-1.8) 26(2.4,-1.4) 27(2.4,-1) 28(2.4,-0.6) 29(2.4,-0.2) 30(2.4,0.6) 31(2.4,1) 32(2.4,1.4) 33(2.4,1.8) 34(2.4,2.2) 35(2.4,2.6)
  rrect50% 0.2x0.6 smd paste+0 mask+0: 14(-1.8,-3.4) 15(-1.4,-3.4) 16(-1,-3.4) 17(-0.6,-3.4) 18(-0.2,-3.4) 19(0.2,-3.4) 20(0.6,-3.4) 21(1,-3.4) 22(1.4,-3.4) 36(1.8,3.4) 37(1.4,3.4) 38(1,3.4) 39(0.6,3.4) 40(0.2,3.4) 41(-0.2,3.4) 42(-0.6,3.4) 43(-1,3.4) 44(-1.4,3.4) 45(-1.8,3.4)
  rrect5% 3.7x2.1 smd paste-1000 mask+0: 46(0,1.4)
  rrect5% 2.9x2.15 smd paste-1000 mask+0: 47(0,-1.375)
  silkscreen extent -3.37,-3.55 2.55,3.55, body extent -2.8,-3.8 2.8,3.8, height 0.25
SM_RADIAL_8MM [mm] "Nichicon 8x10"
  rect 3.5x2.5 smd: 1(-3.25,0) 2(3.25,0)
  silkscreen extent -4.25,-4.25 4.25,4.25, body extent -4.25,-4.25 4.25,4.25, height 10.5
SM_RADIAL_F [mm] "8 x 10.2mm:  Panasonic F"
  rect 4x2 smd: 1(-3.55,0) 2(3.55,0)
  silkscreen extent -4.25,-4.25 4.25,4.25, body extent -4.25,-4.25 4.25,4.25, height 10.5
SMA [mm] "Molded Diode, 2-Leads, Body 4.3x2.6mm, IPC Medium Density, based on OnSemi component dimensions and land pattern"
  rect 2x2 smd: 1(-2,0) 2(2,0)
  silkscreen extent -3.66,-1.57 2.79,1.57, body extent -2.6,-1.3 2.6,1.3, height 2.42
SMB [mil] "Molded Diode, 2-Leads, Body 5.4x3.6mm, IPC Medium Density, based on OnSemi component dimensions"
  rect 85x107.99 smd: 1(-87.01,0) 2(87.01,0)
  silkscreen extent -155,-82 125,82, body extent -106,-71 106,71, height 91
SMC [mil] "Molded Diode, 2-Leads, Body 6.9x5.8mm, IPC Medium Density, based on OnSemi component dimensions and land patterns"
  rect 110x150 smd: 1(-140.49,0) 2(140.49,0)
  silkscreen extent -221,-124 189,123, body extent -156,-116 156,116, height 91
SOD-123 [mm] "On Semi recommended land pattern"
  rect 0.915x1.22 smd: 1(-1.637,0) 2(1.637,0)
  silkscreen extent -2.74,-1.17 2.03,1.17, body extent -1.93,-0.9 1.93,0.9, height 1.35
SOT-23L [mm] "SOT23, 3-Leads, Body 2.9x1.3mm, Pitch 0.95mm, Lead Span 2.5mm, IPC High Density"
  rrect50% 0.8x0.6 smd: 1(-1.1,0.95) 2(-1.1,-0.95) 3(1.1,0)
  silkscreen extent -1.5,-1.5 0.7,1.5, body extent -1.16,-1.45 1.21,1.45, height 1
TEC_1-406541-1 [mm] "TE Connectivity"
  round 1.4 hole 0.89: 1(3.56,-0.18) 2(2.54,1.6) 3(1.52,-0.18) 4(0.5,1.6) 5(-0.52,-0.18) 6(-1.54,1.6) 7(-2.56,-0.18) 8(-3.58,1.6)
  round 2.1 hole 1.57: 9(8.12,0.71) 10(-8.14,0.71)
  round 3.759 hole 3.251: 11(6.34,-2.72) 12(-6.36,-2.72)
  silkscreen extent -9.69,-8 9.69,8.06, body extent -9.33,-8 9.31,7.75, height 14.8
TERM_BLK_ED555-2DS [mil]
  rrect4% 100x100 hole 50: 1(0,0)
  round 100 hole 50: 2(138,0)
  silkscreen extent -93,-161 215,113, body extent -69,-150 207,106, height 323
TRANS_Fairchild_PQFN08A [mm] "Fairchild PQFN08A recommended land pattern"
  rect 1.27x0.61 smd: 1(-2.67,1.905) 2(-2.67,0.635) 3(-2.67,-0.635) 4(-2.67,-1.905) 5(2.67,-1.905) 6(2.67,-0.635) 7(2.67,0.635) 8(2.67,1.905)
  Top Layer region: -1.215,-2.55 2.535,-2.55 2.535,2.55 -1.215,2.55
  silkscreen extent -3.2,-2.7 3.2,2.7, body extent -3.05,-2.55 3.05,2.55, height 1.11
TSW-102-07-G-S [mm] "Samtec 100mil, 1x2, 230 mil above insulator"
  rrect50% 1.65x1.65 hole 1.016: 1(-1.27,0)
  round 1.65 hole 1.016: 2(1.27,0)
  silkscreen extent -3.17,-1.27 2.54,1.27, body extent -2.54,-1.27 2.54,1.27, height 8.38
TSW-103-07-G-S [mm] "Samtec 100mil, 1x3, 230 mil above insulator"
  rrect50% 1.65x1.65 hole 1.016: 1(-2.54,0)
  round 1.65 hole 1.016: 2(0,0) 3(2.54,0)
  body extent -3.81,-1.27 3.81,1.27, height 8.38
WE-HCM_7050 [mm] "WURTH ELEKTRONIK"
  rect 2x3.05 smd: 1(-2.65,0) 2(2.65,0)
  silkscreen extent -3.6,-3.5 3.6,3.5, body extent -3.57,-3.5 3.57,3.5, height 5
WE-SL5 [mm] "SMD, 4-Leads, Body 8.7x10mm"
  rect 2.7x2.7 smd: 1(-3.11,3.81) 2(-3.11,-3.81) 3(3.11,-3.81) 4(3.11,3.81)
  silkscreen extent -4.35,-5 4.35,5.4, body extent -4.35,-5 4.35,5, height 6
WE-TPC-M1 [mm] "Wurth Elektronik recommended land pattern"
  rect 0.5x0.5 smd: 1(-2.35,0) 2(2.325,0)
  Top Layer region: 0.75,1.64 1.005,1.504 1.279,1.279 1.504,1.005 1.671,0.692 1.774,0.353 1.809,0 1.774,-0.353 1.671,-0.692 1.504,-1.005 1.279,-1.279 1.005,-1.504 0.75,-1.64 0.75,-2.65 2.75,-2.65 2.75,2.65 0.75,2.65
  Top Layer region: -0.75,1.64 -1.005,1.504 -1.279,1.279 -1.504,1.005 -1.671,0.692 -1.774,0.353 -1.809,0 -1.774,-0.353 -1.671,-0.692 -1.504,-1.005 -1.279,-1.279 -1.005,-1.504 -0.75,-1.64 -0.75,-2.65 -2.75,-2.65 -2.75,2.65 -0.75,2.65
  silkscreen extent -3,-3 3,3, body extent -2.5,-2.5 2.5,2.5, height 2
WEEE_Minimum [mil] "WEEElie bin"
  silkscreen extent -95,-172 99,104
WL-SMCW_YELLOW [mm] "WURTH"
  rect 0.8x0.8 smd: 1(-0.8,0) 2(0.8,0)
  silkscreen extent -1.9,-0.8 1.2,0.8, body extent -0.85,-0.45 0.85,0.45, height 0.8
Wurth_7490220122 [mm] "SMD, 24-Leads, Body 14.7x18.29mm"
  rect 2.29x0.76 smd: 1(-7.24,6.985) 2(-7.24,5.715) 3(-7.24,4.445) 4(-7.24,3.175) 5(-7.24,1.905) 6(-7.24,0.635) 7(-7.24,-0.635) 8(-7.24,-1.905) 9(-7.24,-3.175) 10(-7.24,-4.445) 11(-7.24,-5.715) 12(-7.24,-6.985) 13(7.24,-6.985) 14(7.24,-5.715) 15(7.24,-4.445) 16(7.24,-3.175) 17(7.24,-1.905) 18(7.24,-0.635) 19(7.24,0.635) 20(7.24,1.905) 21(7.24,3.175) 22(7.24,4.445) 23(7.24,5.715) 24(7.24,6.985)
  silkscreen extent -7.7,-9.15 7.35,9.15, body extent -7.35,-9.15 7.35,9.15, height 8.81

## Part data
C1 C6: library part CMP-0009438-2, "CAP, CERM, 1000 pF, 2000 V, +/- 10%, X7R, 1812", Cap_Case=1812, Manufacturer=MuRata, TempCo=X7R, Tolerance_%=10%, Value1=Unknown, Value2=2000V, ValueDisplayed=1000pF
C2 C3 C4 C5: library part CMP-0007468-5, "CAP, CERM, 0.01 uF, 100 V, +/- 10%, X7R, 0603", Cap_Case=0603, Manufacturer=MuRata, PartNumber=GRM188R72A103KA01D, Supplier Part Number 1=GRM188R72A103KA01D-ND, TempCo=X7R, Tolerance_%=10%, Value1=Unknown, Value2=100V, ValueDisplayed=0.01uF
C7 C8 C9 C23: library part CMP-0007053-4, "CAP, CERM, 1000 pF, 100 V, +/- 10%, X7R, 0603", Cap_Case=0603, Manufacturer=TDK, Supplier Part Number 1=445-1298-1-ND, TempCo=X7R, Tolerance_%=10%, Value1=Unknown, Value2=100V, ValueDisplayed=1000pF
C10: library part CMP-0007461-4, "CAP, CERM, 680 pF, 50 V, +/- 10%, X7R, 0603", Cap_Case=0603, Manufacturer=MuRata, Supplier Part Number 1=490-1491-1-ND, TempCo=X7R, Tolerance_%=10%, Value1=Unknown, Value2=50V, ValueDisplayed=680pF
C11 C28: library part CMP-0009358-2, "CAP, CERM, 2200 pF, 2000 V, +/- 10%, X7R, 1812", Cap_Case=1812, Manufacturer=TDK, PartNumber=C4532X7R3D222K130KA, Supplier Part Number 1=445-2389-1-ND, TempCo=X7R, Tolerance_%=10%, Value1=Unknown, Value2=2000V, ValueDisplayed=2200pF
C12: library part CMP-0011191-2, "CAP, AL, 33 uF, 63 V, +/- 20%, 0.65 ohm, AEC-Q200 Grade 2, SMD", Cap_Case=F, Manufacturer=Panasonic, Supplier Part Number 1=PCE3822CT-ND, Tolerance_%=20%, Value1="0.65 ohm", Value2=63V, ValueDisplayed=33uF
C13 C14: library part CMP-0009232-2, "CAP, CERM, 2.2 uF, 100 V, +/- 10%, X7R, 1210", Cap_Case=1210, Manufacturer=MuRata, PartNumber=GRM32ER72A225KA35L, Supplier Part Number 1=490-3385-1-ND, TempCo=X7R, Tolerance_%=10%, Value1="0.007 ohm", Value2=100V, ValueDisplayed=2.2uF
C15 C30 C43 C45: library part CMP-0007886-2, "CAP, CERM, 0.1 uF, 100 V, +/- 10%, X7R, 0805", Cap_Case=0805, Manufacturer=TDK, PartNumber=C2012X7R2A104K125AA, Supplier Part Number 1=445-1418-1-ND, TempCo=X7R, Tolerance_%=10%, Value1="0.020726 ohm", Value2=100V, ValueDisplayed=0.1uF
C16: library part CMP-0012087-3, "CAP, Aluminum Polymer, 82 uF, 16 V, +/- 20%, 0.04 ohm, 8x10 SMD", Cap_Case=8.3x8.3x6.9, Manufacturer=Panasonic, Tolerance_%=20%, Value1="0.04 ohm", Value2=16V, ValueDisplayed=82uF
C17: library part CMP-0012611-3, "CAP, Tantalum Polymer, 220 uF, 10 V, +/- 20%, 0.025 ohm, 7343-30 SMD", Cap_Case=7343-30, Manufacturer=Panasonic, Supplier Part Number 1=P16451CT-ND, Tolerance_%=20%, Value1="0.025 ohm", Value2=10V, ValueDisplayed=220uF
C18 C19 C20 C21: library part CMP-0064938-2, "CAP, CERM, 10 uF, 25 V,+/- 10%, X7R, 1210", Cap_Case=1210, Manufacturer="Wurth Elektronik", Supplier Part Number 1=732-7729-1-ND, TempCo=X7R, Tolerance_%=10%, Value1=Unknown, Value2=25V, ValueDisplayed=10uF
C22 C37: library part CMP-0006833-4, "CAP, CERM, 1 uF, 25 V, +/- 10%, X7R, 0603", Cap_Case=0603, Manufacturer="Wurth Elektronik", Supplier Part Number 1=732-7994-1-ND, TempCo=X7R, Tolerance_%=10%, Value1=Unknown, Value2=25V, ValueDisplayed=1uF
C24 C25 C27 C29 C31: library part CMP-0007209-4, "CAP, CERM, 330 pF, 50 V, +/- 5%, C0G/NP0, 0603", Cap_Case=0603, Manufacturer=MuRata, Supplier Part Number 1=490-1439-1-ND, TempCo=C0G/NP0, Tolerance_%=5%, Value1=Unknown, Value2=50V, ValueDisplayed=330pF
C33: library part CMP-0007423-5, "CAP, CERM, 0.047 uF, 25 V, +/- 10%, X7R, 0603", Cap_Case=0603, Manufacturer=MuRata, Supplier Part Number 1=490-1522-1-ND, TempCo=X7R, Tolerance_%=10%, Value1=Unknown, Value2=25V, ValueDisplayed=0.047uF
C34: library part CMP-0006792-4, "CAP, CERM, 56 pF, 50 V, +/- 1%, C0G/NP0, 0603", Cap_Case=0603, Manufacturer=AVX, Supplier Part Number 1=478-7922-1-ND, TempCo=C0G/NP0, Tolerance_%=1%, Value1=Unknown, Value2=50V, ValueDisplayed=56pF
C35: library part CMP-0006835-4, "CAP, CERM, 4700 pF, 50 V, +/- 10%, X7R, 0603", Cap_Case=0603, Manufacturer="Wurth Elektronik", Supplier Part Number 1=710-885012206087, TempCo=X7R, Tolerance_%=10%, Value1=Unknown, Value2=50V, ValueDisplayed=4700pF
C36: library part CMP-0006761-4, "CAP, CERM, 10 pF, 50 V, +/- 5%, C0G/NP0, 0603", Cap_Case=0603, Manufacturer=AVX, Supplier Part Number 1=478-1163-1-ND, TempCo=C0G/NP0, Tolerance_%=5%, Value1="0.403 ohm", Value2=50V, ValueDisplayed=10pF
C38 C41: library part CMP-0006832-5, "CAP, CERM, 0.1 uF, 25 V, +/- 10%, X7R, 0603", Cap_Case=0603, Manufacturer="Wurth Elektronik", Supplier Part Number 1=710-885012206071, TempCo=X7R, Tolerance_%=10%, Value1=Unknown, Value2=25V, ValueDisplayed=0.1uF
C39: library part CMP-0006897-4, "CAP, CERM, 2200 pF, 50 V, +/- 10%, X7R, 0603", Cap_Case=0603, Manufacturer=Kemet, Supplier Part Number 1=1362428, TempCo=X7R, Tolerance_%=10%, Value1=Unknown, Value2=50V, ValueDisplayed=2200pF
C40: library part CMP-0008966-2, "CAP, CERM, 3.3 uF, 25 V, +/- 10%, X7R, 1206", Cap_Case=1206, Manufacturer=MuRata, Supplier Part Number 1=GRM31CR71E335KA88L-ND, TempCo=X7R, Tolerance_%=10%, Value1=Unknown, Value2=25V, ValueDisplayed=3.3uF
C42: library part CMP-0064933-4, "CAP, CERM, 1000 pF, 50 V,+/- 10%, X7R, 0603", Cap_Case=0603, Manufacturer="Wurth Elektronik", Supplier Part Number 1=732-8001-1-ND, TempCo=X7R, Tolerance_%=10%, Value1=Unknown, Value2=50V, ValueDisplayed=1000pF
C44: library part CMP-0006737-4, "CAP, CERM, 2200 pF, 100 V, +/- 10%, X7R, 0603", Cap_Case=0603, Manufacturer=AVX, Supplier Part Number 1=478-1201-1-ND, TempCo=X7R, Tolerance_%=10%, Value1="0.192 ohm", Value2=100V, ValueDisplayed=2200pF
D1 D2 D3 D4 D11 D13 D14 D15 D16: "Diode, Schottky, 100 V, 2 A, SMB", Manufacturer="Diodes Inc.", PartNumber=B2100-13-F, Value1=2A, Value2=0.79V
D5 D6 D8 D9 D17: library part CMP-0029032-2, "Diode, Switching, 100 V, 0.2 A, SOD-123", Manufacturer="ON Semiconductor", Value1=0.2A, Value2=1V
D7: library part CMP-0029024-2, "Diode, Ultrafast, 200 V, 1 A, SMA", Manufacturer="Diodes Inc.", Value1=1A, Value2=0.92V
D12: library part CMP-0005486-3, "Diode, TVS, Uni, 58 V, SMA", Manufacturer="Diodes Inc.", Value1=400W
D18 D19: library part CMP-0005751-4, "Diode, Zener, 12 V, 500 mW, SOD-123", Manufacturer="Diodes Inc.", Power_W=500mW, Value1=0.5W
D20: library part CMP-0005513-4, "Diode, Zener, 24 V, 3 W, SMA", Manufacturer="Micro Commercial Components", Power_W=3W
D21 D22 D23: library part CMP-0002892-3, "LED, Yellow, SMD", Color=yellow, Manufacturer="Wurth Elektronik", Value1=W, Value2=2V
D25: library part CMP-0028411-2, "Diode, Schottky, 100 V, 3 A, SMC", Manufacturer="Diodes Inc.", Value1=3A, Value2=0.79V
D100: library part CMP-0029276-2, "Diode, Super Barrier Rectifier, 60 V, 8 A, PowerDI5", Manufacturer="Diodes Inc.", Value1=8A, Value2=0.62V
J1 J2: library part CMP-0054918-1, "RJ45, No LED, tab up, R/A, TH", Color=Black, Manufacturer="TE Connectivity", Supplier Part Number 1=A97716-ND
J3: library part CMP-0074913-1, "Terminal Block, 3.5mm Pitch, 2x1, TH", Color=Grey, Current_A=6A, Manufacturer="On-Shore Technology", Supplier Part Number 1=ED1514-ND, Voltage_V=150V
J4: library part CMP-0074913-1, "Terminal Block, 3.5mm Pitch, 2x1, TH", Color=Grey, Current_A=6A, Manufacturer="On-Shore Technology", PartNumber=ED555/2DS, Supplier Part Number 1=ED1514-ND, Voltage_V=150V
J6 J7 J14: library part CMP-0075407-2, "Header, 100mil, 3x1, Gold, TH", Color=Black, Current_A=6.3A, Manufacturer=Samtec, Supplier Part Number 1=SAM1029-03-ND, Voltage_V=550V
J11: library part CMP-0075087-1, "Jumper Wire, 100mil spacing, pkg of 200, TH", Manufacturer=3M, Supplier Part Number 1=923345-01-ND
J15 J17 J18: library part CMP-0075405-3, "Header, 100mil, 2x1, Gold, TH", Color=Black, Current_A=6.3A, Manufacturer=Samtec, Supplier Part Number 1=SAM1029-02-ND, Voltage_V=550V
L1 L5 L6 L8: "Ferrite Bead, 300 ohm @ 100 MHz, 2 A, 0603", Manufacturer="Wurth Elektronik", PartNumber=742792641, Supplier Part Number 1=732-1592-1-ND, Value1="0.15 ohm", Value2=2A, ValueDisplayed="300 ohm"
L2 L7: library part CMP-0013220-2, "Coupled inductor, 250 uH,  A, 0.035 ohm, SMD", Manufacturer="Wurth Elektronik", Supplier Part Number 1=732-1491-1-ND, ValueDisplayed=250uH
L3: library part CMP-0063798-1, "Inductor, Shielded Drum Core, Ferrite, 3.3 uH, 1.8 A, 0.055 ohm, SMD", Manufacturer="Wurth Elektronik", Supplier Part Number 1=732-1019-1-ND, Value1="0.055 ohm", Value2=1.8A, ValueDisplayed=3.3uH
